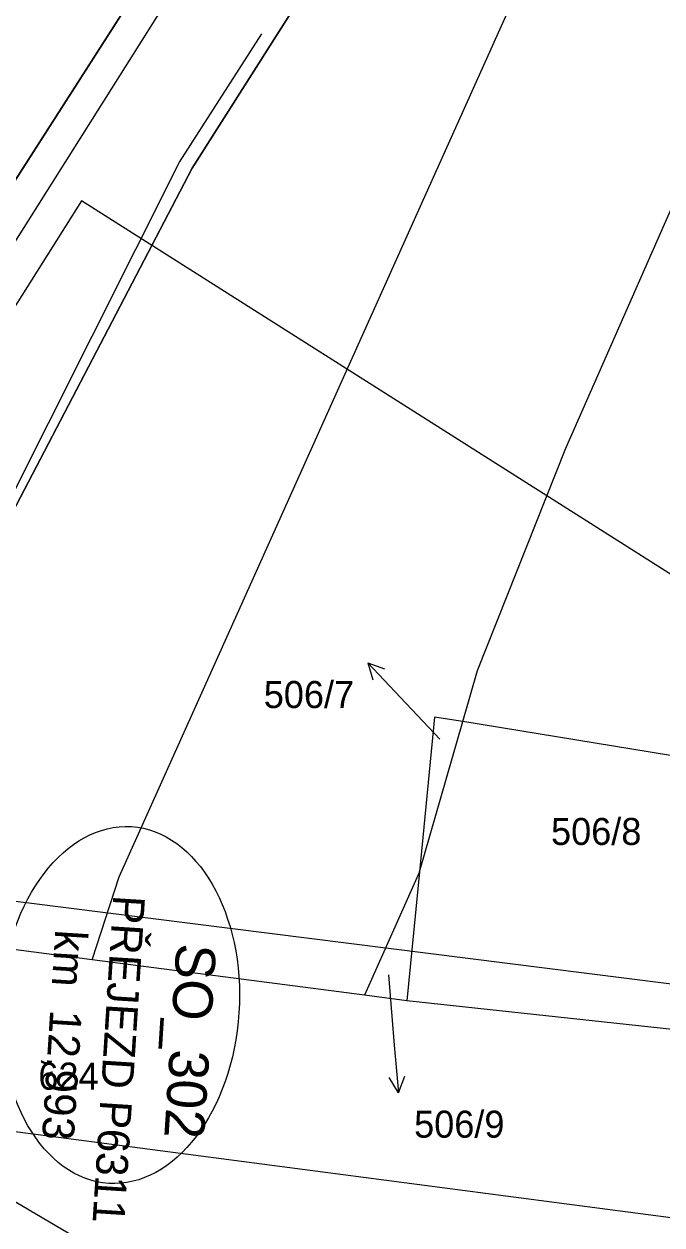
# Model space of a CAD drawing. Extents: x -746176 to -739709, y -1128407 to -1124482.
# Drawn here: x -743147 to -743106.9, y -1127113.6 to -1127038.1 of the extents above; entities that cross this region are included whole.
import ezdxf

# ---------------------------------------------------------------- set-up
doc = ezdxf.new("R2010")
doc.units = 0
for name, color, linetype in [('_Násyp', 7, 'Continuous'), ('_TRASA_vedení kabelu_CEZ', 7, 'Continuous'), ('_Zabezpečovací zařízení_trasa', 7, 'Continuous'), ('bublina_fialová_čára_tenká', 7, 'Continuous'), ('bublina_fialová_čára_tučná', 7, 'Continuous'), ('Hranice parcel', 7, 'Continuous'), ('Parcelní čísla', 7, 'Continuous'), ('Pop  PČ popisy', 7, 'Continuous'), ('SMER_VYS_VYROVNANI', 7, 'Continuous'), ('Vrstva 53', 7, 'Continuous')]:
    doc.layers.add(name, color=color, linetype=linetype)

msp = doc.modelspace()

# ---------------------------------------------------------------- linework, layer by layer
at = {"layer": '_TRASA_vedení kabelu_CEZ'}
for points in [[(-743153.07, -1127080.408), (-743148.258, -1127068.653), (-743137.261, -1127046.755), (-743132.067, -1127038.676)], [(-743154.255, -1127082.611), (-743159.254, -1127091.791), (-743078.983, -1127101.896), (-743017.042, -1127110.608), (-742993.931, -1127114.824), (-742964.817, -1127120.763), (-742937.743, -1127126.541), (-742940.646, -1127140.696), (-742942.997, -1127146.397)]]:
    msp.add_lwpolyline(points, dxfattribs=at)
at = {"layer": '_Zabezpečovací zařízení_trasa'}
msp.add_lwpolyline([(-743018.819, -1126847.736), (-743049.28, -1126895.951), (-743072.487, -1126932.751), (-743098.647, -1126974.146), (-743125.94, -1127017.384), (-743152.604, -1127059.608), (-743175.023, -1127095.116), (-743199.163, -1127133.346), (-743215.971, -1127159.941), (-743232.818, -1127186.515), (-743247.456, -1127209.811), (-743254.52, -1127221.639), (-743261.299, -1127233.691), (-743264.155, -1127239.195), (-743264.862, -1127241.108), (-743267.337, -1127245.816), (-743268.289, -1127247.159), (-743271.711, -1127253.75), (-743281.122, -1127274.196), (-743291.923, -1127301.42), (-743296.724, -1127315.222), (-743301.116, -1127329.128), (-743306.787, -1127349.506)], dxfattribs=at)
at = {"layer": 'bublina_fialová_čára_tenká'}
for p, q in [((-743085.997, -1127085.593), (-743143.427, -1127049.192)), ((-743129.509, -1127122.8), (-743175.485, -1127095.847))]:
    msp.add_line(p, q, dxfattribs=at)
at = {"layer": 'bublina_fialová_čára_tučná'}
msp.add_ellipse((-743140.999, -1127099.794), major_axis=(0.716, 11.227), ratio=0.666667, dxfattribs=at)
at = {"layer": 'Hranice parcel'}
for p, q in [((-743122.16, -1127091.42), (-743119.42, -1127081.96)), ((-743100.51, -1127085.04), (-743119.42, -1127081.96)), ((-743122.16, -1127091.42), (-743125.61, -1127099.18)), ((-743122.16, -1127091.42), (-743122.95, -1127099.53)), ((-743125.61, -1127099.18), (-743142.75, -1127096.94)), ((-743122.95, -1127099.53), (-743125.61, -1127099.18)), ((-743105.44, -1127101.41), (-743122.95, -1127099.53)), ((-743171.62, -1127104.6), (-743100.85, -1127113.88))]:
    msp.add_line(p, q, dxfattribs=at)
for points in [[(-743080.97, -1126930.41), (-743108.67, -1126985.4), (-743124.8, -1127012.28), (-743175.35, -1127091.16), (-743178.51, -1127091.81)], [(-743119.42, -1127081.96), (-743118.49, -1127078.74), (-743112.93, -1127064.74), (-743067.57, -1126961.77), (-743055.18, -1126936.67)], [(-743159.64, -1127094.74), (-743147.78, -1127068.8), (-743136.47, -1127047.12), (-743093.1, -1126978.92), (-743082.27, -1126962.07)], [(-743142.75, -1127096.94), (-743141.05, -1127091.73), (-743109, -1127020.35), (-743082.27, -1126962.07)], [(-743119.42, -1127081.96), (-743121.21, -1127081.67), (-743122.16, -1127091.42)], [(-743142.75, -1127096.94), (-743159.38, -1127094.77), (-743159.64, -1127094.74)]]:
    msp.add_lwpolyline(points, dxfattribs=at)
at = {"layer": 'Pop  PČ popisy'}
for p, q in [((-743123.35, -1127080.45), (-743125.397, -1127078.255)), ((-743125.397, -1127078.255), (-743124.347, -1127078.646)), ((-743125.397, -1127078.255), (-743125.08, -1127079.329)), ((-743120.87, -1127083.07), (-743123.35, -1127080.45)), ((-743124.1, -1127097.89), (-743123.74, -1127102.32)), ((-743123.74, -1127102.32), (-743123.478, -1127105.31)), ((-743123.478, -1127105.31), (-743124.065, -1127104.356)), ((-743123.478, -1127105.31), (-743123.067, -1127104.268))]:
    msp.add_line(p, q, dxfattribs=at)
at = {"layer": 'SMER_VYS_VYROVNANI'}
msp.add_lwpolyline([(-743143.427, -1127049.192), (-743169.53, -1127090.542)], dxfattribs=at)
at = {"layer": 'Vrstva 53'}
msp.add_lwpolyline([(-743032.8, -1126884.17), (-743063.8, -1126932.98), (-743082.27, -1126962.07), (-743093.1, -1126978.92), (-743136.47, -1127047.12), (-743147.78, -1127068.8), (-743159.64, -1127094.74), (-743160.17, -1127095.91), (-743166.78, -1127095.57), (-743176.42, -1127093.47), (-743180.17, -1127093.19), (-743180.08, -1127092.14), (-743178.51, -1127091.81), (-743175.35, -1127091.16), (-743150.075, -1127051.72), (-743124.8, -1127012.28), (-743108.67, -1126985.4), (-743080.97, -1126930.41), (-743079.79, -1126928.05), (-743048.51, -1126865.51), (-743045.12, -1126860.39), (-743029.24, -1126857.99)], dxfattribs=at)

# ---------------------------------------------------------------- texts
at = {"layer": '_Násyp'}
for s, height, p in [('PŘEJEZD P6311', 2, (-743141.419, -1127092.843)), ('km  12,993', 2, (-743145.073, -1127095.022)), ('SO_302', 2.5, (-743137.44, -1127095.871))]:
    msp.add_text(s, height=height, rotation=266.35277, dxfattribs=at).set_placement(p)
at = {"layer": 'Parcelní čísla'}
for s, p in [('506/7', (-743131.956, -1127081.103)), ('506/8', (-743113.87, -1127089.72)), ('624', (-743146.144, -1127105.12)), ('506/9', (-743122.49, -1127108.143))]:
    msp.add_text(s, height=1.7, dxfattribs=at).set_placement(p)

doc.saveas('drawing.dxf')
